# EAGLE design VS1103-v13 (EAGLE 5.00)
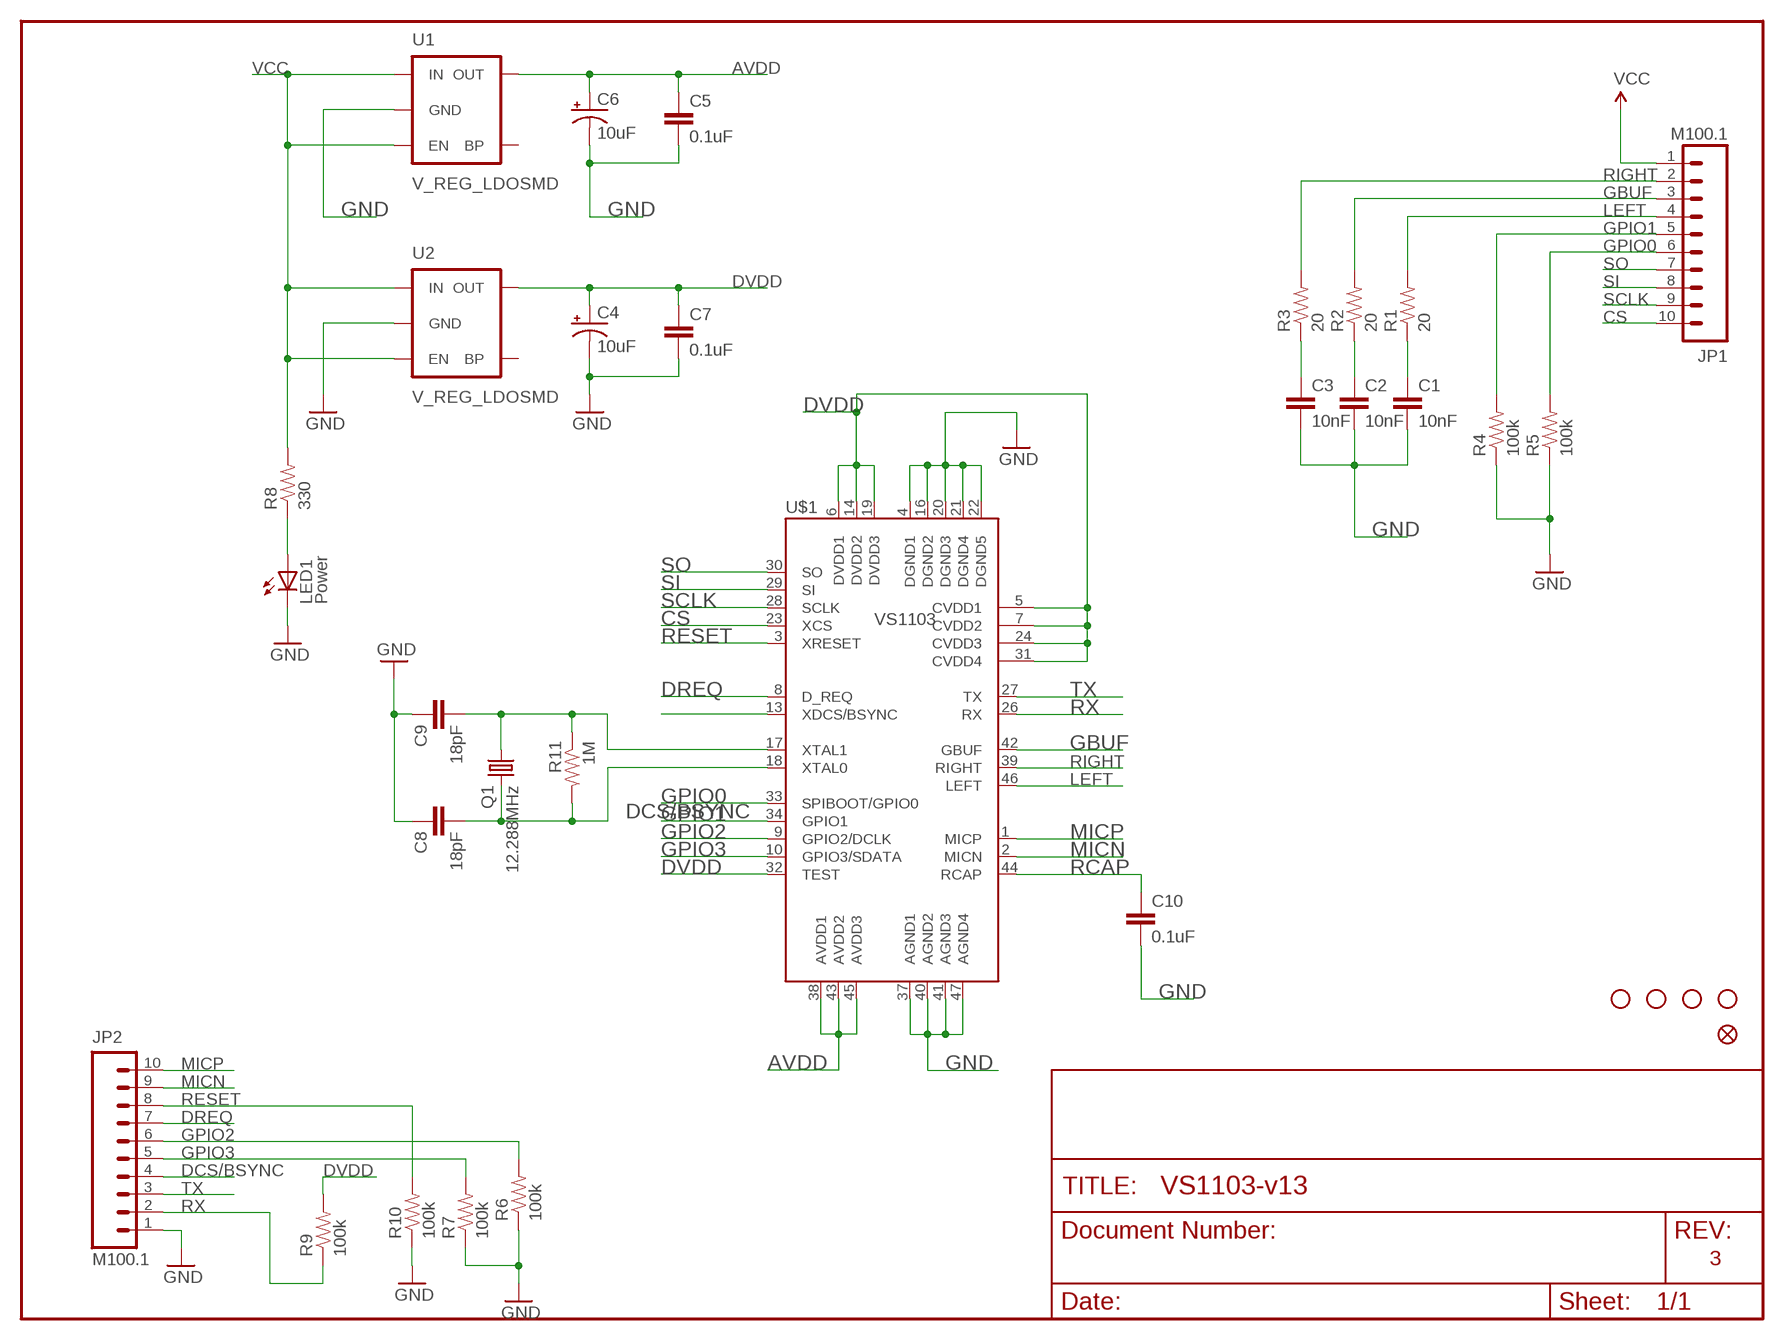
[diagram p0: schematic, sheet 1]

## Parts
C1  10nF  CAP0402  [C0402]
C2  10nF  CAP0402  [C0402]
C3  10nF  CAP0402  [C0402]
C4  10uF  CAP_POL1206  [EIA3216]
C5  0.1uF  CAP0402  [C0402]
C6  10uF  CAP_POL1206  [EIA3216]
C7  0.1uF  CAP0402  [C0402]
C8  18pF  CAP0402  [C0402]
C9  18pF  CAP0402  [C0402]
C10  0.1uF  CAP0402  [C0402]
JP1  M100.1  [1X10]
JP2  M100.1  [1X10]
LED1  Power  LED1206  [LED-1206]
Q1  12.288MHz  CRYSTAL5X3  [CRYSTAL-SMD-5X3]
R1  20  RESISTOR0402  [C0402]
R2  20  RESISTOR0402  [C0402]
R3  20  RESISTOR0402  [C0402]
R4  100k  RESISTOR0402  [C0402]
R5  100k  RESISTOR0402  [C0402]
R6  100k  RESISTOR0402  [C0402]
R7  100k  RESISTOR0402  [C0402]
R8  330  RESISTOR0402  [C0402]
R9  100k  RESISTOR0402  [C0402]
R10  100k  RESISTOR0402  [C0402]
R11  1M  RESISTOR  [0805]
U1  V_REG_LDOSMD  [SOT23-5]
U2  V_REG_LDOSMD  [SOT23-5]
U$1  VS1103  [LQFP-48]
U$6  FIDUCIAL1X2  [FIDUCIAL-1X2]
U$8  STAND-OFF  [STAND-OFF]
U$9  STAND-OFF  [STAND-OFF]
U$10  STAND-OFF  [STAND-OFF]
U$11  STAND-OFF  [STAND-OFF]

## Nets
AVDD: C5.1 C6.A(+) U1.5(OUT) U$1.38(AVDD1) U$1.43(AVDD2) U$1.45(AVDD3)
CS: JP1.10 U$1.23(XCS)
DCS/BSYNC: JP2.4 U$1.13(XDCS/BSYNC)
DREQ: JP2.7 U$1.8(D_REQ)
DVDD: C4.A(+) C7.1 R9.2 U2.5(OUT) U$1.5(CVDD1) U$1.6(DVDD1) U$1.7(CVDD2) U$1.14(DVDD2) U$1.19(DVDD3) U$1.24(CVDD3) U$1.31(CVDD4) U$1.32(TEST)
GBUF: JP1.3 R2.2 U$1.42(GBUF)
GND: C1.2 C2.2 C3.2 C4.C(-) C5.2 C6.C(-) C7.2 C8.1 C9.1 C10.2 JP2.1 LED1.C R4.1 R5.1 R6.1 R7.1 R10.1 U1.2(GND) U2.2(GND) U$1.4(DGND1) U$1.16(DGND2) U$1.20(DGND3) U$1.21(DGND4) U$1.22(DGND5) U$1.37(AGND1) U$1.40(AGND2) U$1.41(AGND3) U$1.47(AGND4)
GPIO0: JP1.6 R5.2 U$1.33(SPIBOOT/GPIO0)
GPIO1: JP1.5 R4.2 U$1.34(GPIO1)
GPIO2: JP2.6 R6.2 U$1.9(GPIO2/DCLK)
GPIO3: JP2.5 R7.2 U$1.10(GPIO3/SDATA)
LEFT: JP1.4 R1.2 U$1.46(LEFT)
MICN: JP2.9 U$1.2(MICN)
MICP: JP2.10 U$1.1(MICP)
N$1: C1.1 R1.1
N$2: C2.1 R2.1
N$3: C3.1 R3.1
N$6: LED1.A R8.1
N$7: C8.2 Q1.3 R11.2 U$1.18(XTAL0)
N$8: C9.2 Q1.1 R11.1 U$1.17(XTAL1)
RCAP: C10.1 U$1.44(RCAP)
RESET: JP2.8 R10.2 U$1.3(XRESET)
RIGHT: JP1.2 R3.2 U$1.39(RIGHT)
RX: JP2.2 R9.1 U$1.26(RX)
SCLK: JP1.9 U$1.28(SCLK)
SI: JP1.8 U$1.29(SI)
SO: JP1.7 U$1.30(SO)
TX: JP2.3 U$1.27(TX)
VCC: JP1.1 R8.2 U1.1(IN) U1.3(EN) U2.1(IN) U2.3(EN)
Unconnected: U1.4(BP) U2.4(BP)

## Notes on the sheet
- 3

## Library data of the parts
C1-C3 C5 C7-C10 = SparkFun:CAP: Capacitor
C4 C6 = SparkFun:CAP_POL: Capacitor Polarized
JP1 JP2 = SparkFun:M10: Header 10 Standard 10-pin 0.1" header. Use with straight break away headers (SKU : PRT-00116), right angle break away headers (PRT-00553), swiss pins (PRT-00743), machine pins (PRT-00117), and female headers (PRT-00115).
LED1 = SparkFun:LED: LEDs
Q1 = SparkFun:CRYSTAL: Crystals
R1-R11 = SparkFun:RESISTOR: Resistor
U1 U2 = SparkFun:V_REG_LDO: Voltage Regulator LDO Standard 150mA LDO voltage regulator in SOT-23 layout. Micrel part MIC5205. BP (by-pass) pin is used to lower output noise with 470pF cap.
U$1 = SparkFun:VS1103
U$6 = SparkFun:FIDUCIAL: Fiducial Alignment Points
U$8-U$11 = SparkFun:STAND-OFF: Stand Off

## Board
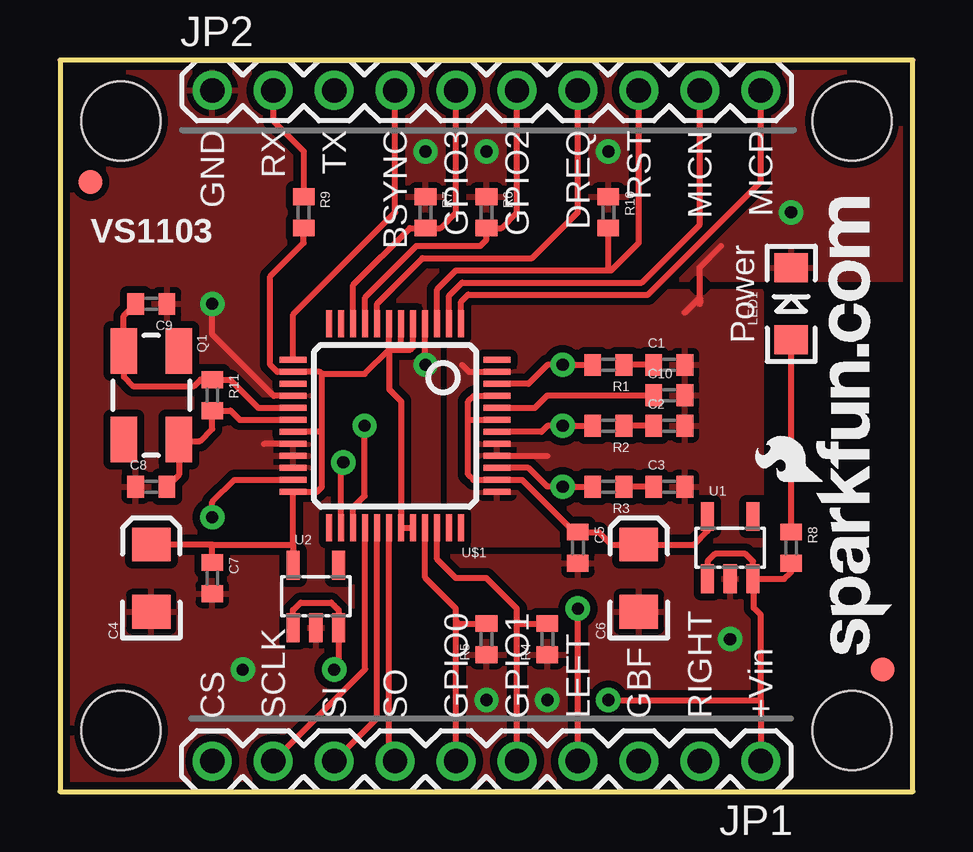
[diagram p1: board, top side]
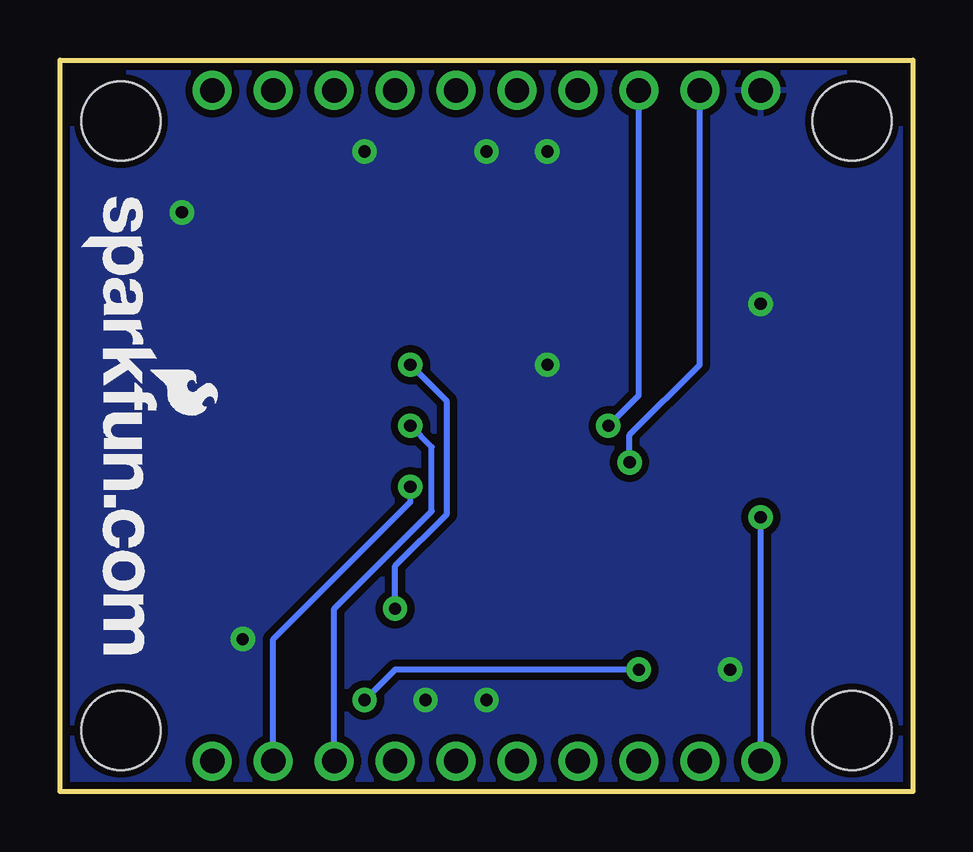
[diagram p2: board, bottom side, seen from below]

Size 35.56 x 30.48 mm. Coordinates in mm from the lower left corner, seen from the top.
Outline: 0,30.48 0,0 35.56,0 35.56,30.48 0,30.48
Copper layers (1*16): Top 0.035mm / dielectric 1.5mm / Bottom 0.035mm
Design rules "SparkFun": minimum track width 8mil, minimum drill 20mil, track to track 8mil, track to pad 8mil, pad to pad 8mil, via to via 8mil, smd to smd 8mil, copper to edge 10mil, drill to drill 8mil, minimum pad ring 12mil, minimum via ring 10mil, stop-mask expansion 4mil, vias tented up to drill 25mil, thermal gap 10mil

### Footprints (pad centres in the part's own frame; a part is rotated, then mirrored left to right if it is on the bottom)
C0402 = smd 0.7 x 0.9: 1 -0.65,0; 2 0.65,0
EIA3216 = smd 1.4 x 1.6: A 1.4,0; C -1.4,0
1X10 = drill 1.016 round: 1 0,0; 2 2.54,0; 3 5.08,0; 4 7.62,0; 5 10.16,0; 6 12.7,0; 7 15.24,0; 8 17.78,0; 9 20.32,0; 10 22.86,0
LED-1206 = smd 1.2 x 1.4: A -1.5,0; C 1.5,0
CRYSTAL-SMD-5X3 = smd 1.9 x 1.1: 1 -1.85,-1.15; 2 1.85,-1.15; 3 1.85,1.15; 4 -1.85,1.15
SOT23-5 = smd 0.55 x 1.2: 1 -0.95,-1.3; 2 0,-1.3; 3 0.95,-1.3; 4 0.95,1.3; 5 -0.95,1.3
LQFP-48 = smd 0.254 x 1.143: 1 -2.75,-4.25; 2 -2.25,-4.25; 3 -1.75,-4.25; 4 -1.25,-4.25; 5 -0.75,-4.25; 6 -0.25,-4.25; 7 0.25,-4.25; 8 0.75,-4.25; 9 1.25,-4.25; 10 1.75,-4.25; 11 2.25,-4.25; 12 2.75,-4.25; 25 2.75,4.25; 26 2.25,4.25; 27 1.75,4.25; 28 1.25,4.25; 29 0.75,4.25; 30 0.25,4.25; 31 -0.25,4.25; 32 -0.75,4.25; 33 -1.25,4.25; 34 -1.75,4.25; 35 -2.25,4.25; 36 -2.75,4.25 | smd 1.143 x 0.254: 13 4.25,-2.75; 14 4.25,-2.25; 15 4.25,-1.75; 16 4.25,-1.25; 17 4.25,-0.75; 18 4.25,-0.25; 19 4.25,0.25; 20 4.25,0.75; 21 4.25,1.25; 22 4.25,1.75; 23 4.25,2.25; 24 4.25,2.75; 37 -4.25,2.75; 38 -4.25,2.25; 39 -4.25,1.75; 40 -4.25,1.25; 41 -4.25,0.75; 42 -4.25,0.25; 43 -4.25,-0.25; 44 -4.25,-0.75; 45 -4.25,-1.25; 46 -4.25,-1.75; 47 -4.25,-2.25; 48 -4.25,-2.75
FIDUCIAL-1X2 = smd 1 x 1: 1 0,0
STAND-OFF = hole 3.302: 0,0

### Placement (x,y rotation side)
C1  25.4,17.78 0 top
C2  25.4,15.24 0 top
C3  25.4,12.7 0 top
C4  3.81,8.89 90 top
C5  21.59,10.16 270 top
C6  24.13,8.89 90 top
C7  6.35,8.89 270 top
C8  3.81,12.7 0 top
C9  3.81,20.32 180 top
C10  25.4,16.51 0 top
JP1  29.21,1.27 180 top
JP2  6.35,29.21 0 top
LED1  30.48,20.32 90 top
Q1  3.81,16.51 270 top
R1  22.86,17.78 180 top
R2  22.86,15.24 180 top
R3  22.86,12.7 180 top
R4  20.32,6.35 90 top
R5  17.78,6.35 90 top
R6  17.78,24.13 270 top
R7  15.24,24.13 270 top
R8  30.48,10.16 270 top
R9  10.16,24.13 270 top
R10  22.86,24.13 270 top
R11  1M  [C0402]  6.35,16.51 270 top
U1  27.94,10.16 0 top
U2  10.67,8.13 0 top
U$1  13.97,15.24 180 top
U$2  LOGO-SFENEW  [SFE-NEW-WEBLOGO]  34.67,24.77 270 bottom
U$5  LOGO-SFENEW  [SFE-NEW-WEBLOGO]  34.67,5.71 90 top
U$6  1.27,25.4 0 top
U$7  FIDUCIAL1X2  [FIDUCIAL-1X2]  34.29,5.08 0 top
U$8  33.02,2.54 0 top
U$9  2.54,27.94 0 top
U$10  33.02,27.94 0 top
U$11  2.54,2.54 0 top

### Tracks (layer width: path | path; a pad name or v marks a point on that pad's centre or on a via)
AVDD
  Top 0.254: C5.1 21.59,10.79 | 26.89,11.56 U1.5 26.99,10.86 26.42,10.29 C6.A 22.98,10.29 22.46,10.81 C5.1 | U$1.45 17.25,16.49 17.02,16.26 17.02,15.49 | 17.02,15.49 17.02,13.21 17.24,12.99 U$1.38 19.27,12.99 21.45,10.81 C5.1 | U$1.43 17.02,15.49
CS  (via drill 0.51)
  Top 0.254: U$1.23 7.28,12.99 6.35,12.06 v6.35,11.43
  Bottom 0.254: JP1.10 v6.35,11.43
DCS/BSYNC
  Top 0.254: U$1.13 9.72,19.88 13.97,24.13 JP2.4
DREQ
  Top 0.254: JP2.7 21.59,24.13 19.68,22.23 15.11,22.23 13.22,20.33 U$1.8
DVDD
  Top 0.254: 6.35,9.53 C7.1 6.35,10.29 | 13.72,19.94 U$1.7 13.72,18.41 | U$1.32 U$1.31 14.22,16.26 13.72,16.76 13.72,18.41 | 10.92,14.99 10.92,16.26 | 10.92,16.26 10.92,17.4 | 10.92,16.26 | R9.2 10.16,22.86 8.76,21.46 8.76,17.78 9.05,17.49 U$1.14 10.83,17.49 10.92,17.4 | U$1.19 10.92,14.99 | 10.92,14.99 10.92,12.7 10.71,12.49 U$1.24 9.72,10.29 | 9.72,10.29 U2.5 | 6.35,10.29 C4.A | 6.35,10.29 9.71,10.29 9.72,10.29 | U$1.5 14.72,18.53 14.61,18.41 14.1,18.41 | 13.72,18.41 14.1,18.41 | U$1.6 14.22,18.54 14.1,18.41 | 13.72,18.41 12.7,17.4 10.92,17.4
GBUF  (via drill 0.51)
  Top 0.254: U$1.42 20.07,14.99 20.32,15.24 v20.95,15.24 R2.2
  Bottom 0.254: JP1.3 24.13,7.62 20.07,11.68 20.07,14.35 v20.95,15.24
GND  (via drill 0.51)
  Top 0.254: LED1.C 30.48,21.72 | 26.67,20.83 26.67,21.84 27.56,22.73 | 21.59,9.53 C5.2 21.35,9.51 | 26.67,20.57 26.67,20.32 | 26.67,20.57 26.67,20.83 | 26.67,20.83 26.67,20.95 | 26.05,19.95 26.67,20.57 | 15.22,17.76 U$1.4 | U$1.40 20.3,13.99 20.32,13.97 | U$1.16 8.91,16.49 6.35,19.05 v6.35,20.32 | U$1.47 17.05,17.49 16.76,17.78 | U$1.20 8.52,14.49 8.51,14.48
  other vias: 7.62,5.08 20.32,3.81 30.48,24.13 22.86,26.67 15.24,17.78 15.24,26.67 17.78,3.81 27.94,6.35 17.78,26.67
  pour Bottom (isolate 0.305): 0,30.48 0,0 35.43,0 35.56,30.48
  pour Top (isolate 0.305): 0,30.48 35.56,30.48 35.56,21.34 27.18,21.34 26.92,21.59 26.42,21.59 26.16,21.34 15.75,21.34 15.75,9.78 35.56,9.78 35.56,0 0,0
  pour Top (isolate 0.305): 16.26,20.83 26.16,20.83 26.42,20.57 26.92,20.57 27.18,20.83 29.21,20.83 29.21,10.29 16.26,10.29
GPIO0
  Top 0.254: U$1.33 15.22,8.91 16.51,7.62 16.51,7.11 | JP1.6 16.51,7.11 | R5.2 16.62,7 16.51,7.11
GPIO1
  Top 0.254: U$1.34 15.72,9.68 16.51,8.89 17.78,8.89 19.05,7.62 19.05,7.11 | JP1.5 19.05,7.11 | R4.2 19.16,7 19.05,7.11
GPIO2
  Top 0.254: U$1.9 12.72,20.59 14.86,22.73 17.53,22.73 17.78,22.99 R6.2 18.4,23.48 19.05,24.13 JP2.6
GPIO3
  Top 0.254: U$1.10 12.22,21.11 14.59,23.48 R7.2 15.86,23.48 16.51,24.13 JP2.5
LEFT  (via drill 0.51)
  Top 0.254: U$1.46 19.53,16.99 20.32,17.78 v20.95,17.78 R1.2 | JP1.4 v21.59,7.62
  Bottom 0.254: v20.95,17.78 19.43,16.26 19.43,11.56 21.59,9.4 v21.59,7.62
MICN
  Top 0.254: JP2.9 26.67,23.62 24.26,21.21 16.76,21.21 16.22,20.66 U$1.2
MICP
  Top 0.254: JP2.10 29.21,25.4 24.51,20.7 17.02,20.7 16.72,20.4 U$1.1
N$1
  Top 0.254: C1.1 R1.1
N$2
  Top 0.254: C2.1 R2.1
N$3
  Top 0.254: C3.1 R3.1
N$6
  Top 0.254: R8.1 LED1.A
N$7
  Top 0.254: C8.2 4.96,13.2 Q1.3 5.01,14.61 5.84,14.61 6.35,15.11 R11.2 6.37,15.88 7.11,15.88 7.5,15.49 U$1.18
N$8
  Top 0.254: U$1.17 8.27,15.99 7.1,17.16 R11.1 5.86,17.16 5.59,16.89 3.05,16.89 2.67,17.27 Q1.1 2.66,19.82 C9.2
RCAP
  Top 0.254: U$1.44 19.8,15.99 20.32,16.51 C10.1
RESET
  Top 0.254: JP2.8 24.13,22.86 22.99,21.72 22.86,21.72 | U$1.3 15.72,20.93 16.51,21.72 22.86,21.72 | 22.86,21.72 R10.2
RIGHT  (via drill 0.51)
  Top 0.254: U$1.39 19.53,13.49 20.32,12.7 v20.95,12.7 R3.2
  Bottom 0.254: JP1.2 26.67,6.35 20.95,12.06 v20.95,12.7
RX  (via drill 0.51)
  Top 0.254: R9.1 10.16,26.67 8.89,27.94 JP2.2 | U$1.26 11.72,13.62 v11.81,13.72
  Bottom 0.254: v11.81,13.72 11.81,14.86 8.89,17.78 JP2.2
SCLK
  Top 0.254: U$1.28 12.72,5.1 JP1.9
SI
  Top 0.254: U$1.29 13.22,3.06 JP1.8
SO
  Top 0.254: U$1.30 13.72,1.52 JP1.7
TX  (via drill 0.51)
  Top 0.254: U$1.27 12.22,11.84 12.7,12.32 v12.7,15.24
  Bottom 0.254: JP2.3 11.43,16.51 v12.7,15.24
VCC  (via drill 0.51)
  Top 0.254: U1.3 28.93,8.86 28.93,7.65 29.21,7.37 29.21,3.81 | U2.1 9.72,7.56 10.03,7.87 11.3,7.87 11.43,7.75 | 11.43,7.75 11.56,7.62 | 11.43,7.75 11.62,7.56 U2.3 11.62,5.27 v11.43,5.08 | R8.2 30.48,9.14 30.2,8.86 U1.3 | U1.1 26.99,9.59 27.3,9.91 28.57,9.91 28.89,9.59 U1.3 | v22.86,3.81 29.21,3.81 | 29.21,3.81 JP1.1
  Bottom 0.254: v22.86,3.81 21.59,5.08 v11.43,5.08

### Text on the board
tPlace: GND | RX | TX | BSYNC | GPIO3 | GPIO2 | DREQ | RST | MICN | MICP | VS1103 | Power | CS | SCLK | SI | SO | GPIO0 | GPIO1 | LEFT | GBF | RIGHT | +Vin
